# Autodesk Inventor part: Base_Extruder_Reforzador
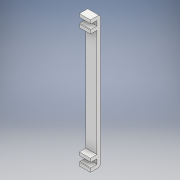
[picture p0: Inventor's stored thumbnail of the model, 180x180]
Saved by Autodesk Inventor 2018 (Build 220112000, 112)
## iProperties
Part Number: Base_Extruder_Reforzador
Material: Plástico ABS
Document SubType Name: Modeling
Designer: ULISES
Density: 1.06 g/cm^3
Appearance: Valor por defecto(1)
Mass: 170.779 g
Surface Area: 663.504 cm^2
Volume: 161.112 cm^3
Author: ULISES
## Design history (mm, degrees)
sketch "Boceto1"
  geometry: L1 (0, 0)-(60, 0); L2 (60, 0)-(60, 49); L3 (60, 49)-(0, 49); L4 (0, 49)-(0, 0); C1 r 1.6 at (50, 29); C2 r 1.6 at (10, 29); C3 r 12.5 at (30, 21); C4 r 13.5 at (30, -2); C5 r 1.6 at (45.5, 36.5); C6 r 1.6 at (14.5, 36.5); C7 r 1.6 at (45.5, 5.5); C8 r 1.6 at (14.5, 5.5)
  constraints: 8 centre point, 8 end point, 2 horizontal, 2 parallel, 1 horizontal alignment, 1 perpendicular, 1 vertical, 1 vertical alignment, 6 other
  dimensions: "d0" = 3.2 diameter of C1; "d1" = 3.2 diameter of C2 (= d0); "d2" = 25 diameter of C3; "d3" = 27 diameter of C4; "d10" = 20 horizontal distance of C3.centre C2.centre (= 0.5 x d15); "d14" = 60 distance of L2.end L3.end; "d15" = 40 distance of C2.centre C1.centre; "d16" = 10 distance from line of L4 C2.centre (= 0.5 x d14 - 0.5 x d15); "d17" = 3.2 diameter of C5; "d20" = 31 distance of C5.centre C6.centre; "d23" = 31 distance of C5.centre C7.centre; "d26" = 15.5 horizontal distance of C5.centre C3.centre (= 0.5 x d20); "d27" = 15.5 horizontal distance of C5.centre C3.centre (= 0.5 x d23); "d47" = 23 distance of C4.centre C3.centre; "d48" = 49 distance of L3.end L1.start; "d50" = 28 distance from line of L3 C3.centre; "d51" = 20 distance from line of L3 C1.centre; "d52" = 8 vertical distance of C3.centre C1.centre (derived)
extrude "Extrusión1" new body sketch "Boceto1" distance "d28" = 5; taper "d29" = 0 deg
sketch "Boceto2"
  geometry: C1 r 1.6 at (10, 29) reference; C2 r 1.6 at (50, 29) reference; C3 r 4.15 at (10, 29); C4 r 4.15 at (50, 29); 1 further point
  constraints: 2 centre point, 2 coincident
  dimensions: "d32" = 8.3 diameter of C3; "d33" = 8.3 diameter of C4
extrude "Extrusión2" cut sketch "Boceto2" distance "d30" = 6; taper "d31" = 0 deg
sketch "Boceto3"
  geometry: L1 (0, 0)-(-60, 0) reference; L2 (0, 49)-(0, 0) reference; L3 (-60, 49)-(0, 49) reference; L4 (-60, 0)-(-60, 49) reference; L5 (-60, 0)-(-60, 49) reference; L6 (-60, 49)-(0, 49); L7 (0, 49)-(0, 43); L8 (0, 43)-(-60, 43); L9 (-60, 43)-(-60, 49); C1 r 12.5 at (-30, 21) reference; C2 r 1.6 at (-14.5, 5.5) reference; C3 r 1.6 at (-45.5, 5.5) reference; C4 r 1.6 at (-14.5, 36.5) reference; C5 r 1.6 at (-45.5, 36.5) reference; 1 further point
  constraints: 8 end point, 2 parallel, 1 horizontal, 1 perpendicular, 1 point on line
  dimensions: "d34" = 6 distance between parallel lines of L3 L8
extrude "Extrusión3" join sketch "Boceto3" distance "d35" = 125; taper "d36" = 0 deg
sketch "Boceto4"
  geometry: L1 (0, 43)-(-60, 43) reference; L2 (-60, 0)-(-60, 43) reference; L3 (0, 0)-(-60, 0) reference; L4 (0, 43)-(0, 0) reference; L5 (0, 43)-(0, 49) reference; L6 (0, 49)-(-60, 49) reference; L7 (-60, 49)-(-60, 43) reference; L8 (-60, 43)-(0, 43) reference; L9 (-60, 0)-(-60, -13); L10 (-60, -13)-(0, -13); L11 (0, -13)-(0, 0); L12 (0, 0)-(-19.285, 0); L13 (-40.715, 0)-(-60, 0); L14 (0, 49)-(0, 0) reference; L15 (0, 0)-(0, 49); L16 (0, 49)-(-60, 49); L17 (-60, 49)-(-60, 0); L18 (-60, 0)-(-40.715, 0); L19 (-19.285, 0)-(0, 0); L20 (-30, -2)-(-40.9, -2); L21 (-40.9, -2)-(-40.9, -13); L22 (-40.9, -13)-(-30, -13); L23 (-30, -13)-(-30, -2); L24 (-30, -2)-(-19.1, -2); L25 (-19.1, -2)-(-19.1, -13); L26 (-19.1, -13)-(-30, -13); L27 (-30, -13)-(-30, -2); C1 r 12.5 at (-30, 21) reference; C2 r 1.6 at (-14.5, 5.5) reference; C3 r 1.6 at (-45.5, 5.5) reference; C4 r 1.6 at (-14.5, 36.5) reference; C5 r 1.6 at (-45.5, 36.5) reference; C6 r 4.5 at (-30, 21); A1 r 10.9 centre (-30, -2) between (-19.285, 0) and (-40.715, 0)
  constraints: 36 end point, 10 parallel, 6 horizontal, 6 perpendicular, 2 centre point, 2 collinear, 2 point on circle, 2 tangent, 1 coincident, 1 point on line, 1 vertical alignment
  dimensions: "d37" = 9 diameter of C6; "d54" = 13 distance of L9.start L9.end; "d55" = 60 distance of L9.end L10.end; "d62" = 23 distance of L20.start C1.centre; "d63" = 21.8 diameter of A1
extrude "Extrusión4" join sketch "Boceto4" distance "d39" = 5; taper "d40" = 0 deg
sketch "Boceto5"
  geometry: C1 r 4.15 at (-10, 29) reference; C2 r 4.15 at (-50, 29) reference; C3 r 6.15 at (-10, 29); C4 r 6.15 at (-50, 29); 1 further point
  constraints: 2 centre point
  dimensions: "d175" = 2 radial gap between concentric circles of C3 C1; "d176" = 2 radial gap between concentric circles of C2 C4
extrude "Extrusión5" join sketch "Boceto5" distance "d41" = 10; taper "d42" = 0 deg
sketch "Boceto6"
  geometry: L1 (-60, 43)-(0, 43) reference; L2 (-60, 43)-(0, 43); L3 (0, 43)-(0, 49); L4 (0, 49)-(-60, 49); L5 (-60, 49)-(-60, 43); L6 (-60, -13)-(-40.9, -13) reference; L7 (0, -13)-(0, 49) reference; L8 (0, 49)-(-60, 49) reference; L9 (-60, 49)-(-60, -13) reference; L10 (-40.9, -13)-(-40.9, -2) reference; L11 (-19.1, -2)-(-19.1, -13) reference; L12 (-19.1, -13)-(0, -13) reference; L13 (-40.9, -2)-(-19.1, -2) reference; C1 r 4.5 at (-30, 21) reference; 1 further point
  constraints: 8 end point, 2 parallel, 1 horizontal, 1 perpendicular
extrude "Extrusión6" join sketch "Boceto6" distance "d43" = 70; taper "d44" = 0 deg
sketch "Boceto7"
  geometry: L1 (0, 43)-(-60, 43) reference; L2 (-60, 43)-(0, 43) reference; L3 (0, 43)-(0, 49) reference; L4 (0, 49)-(-60, 49) reference; L5 (-60, 49)-(-60, 43) reference; L6 (-60, -13)-(-40.9, -13) reference; L7 (-60, 43)-(-60, -13) reference; L8 (0, -13)-(0, 43) reference; L9 (-40.9, -13)-(-40.9, -2) reference; L10 (-19.1, -2)-(-19.1, -13) reference; L11 (-60, -13)-(-40.9, -13) reference; L12 (-40.9, -2)-(-60, -2); L13 (-19.1, -2)-(0, -2); L14 (-60, 49)-(0, 49) reference; L15 (0, -2)-(0, 49); L16 (0, 49)-(-60, 49); L17 (-60, 49)-(-60, -2); L18 (-60, -2)-(-40.9, -2); L19 (-19.1, -2)-(0, -2); L20 (-19.1, -13)-(0, -13) reference; L21 (-40.9, -2)-(-19.1, -2) reference; C1 r 4.5 at (-30, 21) reference; A1 r 10.9 centre (-30, -2) between (-19.1, -2) and (-40.9, -2); 1 further point
  constraints: 14 end point, 3 horizontal, 3 parallel, 2 perpendicular, 2 point on circle, 1 centre point
  dimensions: "d177" = 10.9 radius of A1
extrude "Extrusión7" join sketch "Boceto7" distance "d45" = 5; taper "d46" = 0 deg
sketch "Boceto8"
  geometry: C1 r 1.6 at (-45.5, 5.5) reference; C2 r 1.6 at (-45.5, 36.5) reference; C3 r 1.6 at (-14.5, 36.5) reference; C4 r 1.6 at (-14.5, 5.5) reference; C5 r 3 at (-45.5, 5.5); C6 r 3 at (-45.5, 36.5); C7 r 3 at (-14.5, 36.5); C8 r 1.6 at (-14.5, 5.5) reference; C9 r 3 at (-14.5, 5.5); 1 further point
  constraints: 4 centre point, 4 coincident
  dimensions: "d56" = 6 diameter of C5; "d57" = 6 diameter of C6; "d58" = 6 diameter of C7; "d59" = 6 diameter of C9
extrude "Extrusión8" cut sketch "Boceto8" distance "d60" = 2.5; taper "d61" = 0 deg
sketch "Boceto9"
  geometry: L1 (18.5, 1)-(38.5, 1); L2 (38.5, 11)-(21.5, 11); L3 (48.5, 1)-(48.5, -13); L4 (11.5, -13)-(11.5, 1); L5 (9.5, -13)-(9.5, 1); L6 (21.5, 13)-(38.5, 13); L7 (50.5, 1)-(50.5, -13); L8 (48.5, -13)-(50.5, -13); L9 (9.5, -13)-(11.5, -13); L10 (19.1, -2)-(40.9, -2) reference; L11 (19.1, -13)-(19.1, -2) reference; L12 (19.1, -13)-(0, -13) reference; L13 (60, -13)-(40.9, -13) reference; L14 (40.9, -2)-(40.9, -13) reference; A1 r 10 centre (38.5, 1) between (48.5, 1) and (38.5, 11); A2 r 10 centre (21.5, 1) between (21.5, 11) and (11.5, 1); A3 r 12 centre (21.5, 1) between (21.5, 13) and (9.5, 1); A4 r 12 centre (38.5, 1) between (50.5, 1) and (38.5, 13); 1 further point
  constraints: 19 end point, 8 point on circle, 4 centre point, 4 tangent, 2 collinear, 2 parallel, 1 point on line, 4 other
  dimensions: "d64" = 20 distance of L1.start L1.end; "d66" = 2 radial gap between concentric circles of A1 A4; "d183" = 37 distance between parallel lines of L3 L4; "d184" = 21.8 distance between parallel lines of L14 L11 (derived); "d185" = 7.6 distance between parallel lines of L4 L11 (= 0.5 x d183 - 0.5 x d184); "d186" = 13 distance between parallel lines of L10 L2; "d187" = 10 radius of A2; "d188" = 10 radius of A1
extrude "Extrusión9" join sketch "Boceto9" distance "d67" = 2.2; taper "d68" = 0 deg
sketch "Boceto11" dims "d104" = 10.9 (derived)
  geometry: L1 (44, -2)-(54, -2); L2 (54, -2)-(54, 1); L3 (54, 1)-(43.572, 1); L4 (44, 1)-(44, -2); L5 (19.1, -2)-(9.1, -2); L6 (9.1, -2)-(9.1, 3); L7 (9.1, 3)-(17.03, 3); L8 (19.1, -2)-(0, -2) reference; L9 (19.1, -2)-(9.1, -2); L10 (9.1, -2)-(9.1, -7); L11 (9.1, -7)-(19.1, -7); L12 (19.1, -7)-(19.1, -2); L13 (60, -2)-(40.9, -2) reference; L14 (44, -2)-(40.9, -2); A1 r 13.9 centre (30, -2) between (43.572, 1) and (17.03, 3); 2 further points
  constraints: 24 end point, 4 horizontal, 4 parallel, 3 perpendicular, 2 point on circle, 1 centre point, 1 collinear, 1 vertical, 2 other
  dimensions: "d71" = 3 dimension on A1; "d72" = 3 distance of L1.end L2.end; "d73" = 10 distance of L2.end L4.start; "d75" = 5 distance of L5.end L6.end; "d84" = 10 distance from line of L6 L5.start; "d106" = 5 distance of L9.end L10.end; "d107" = 10 distance of L10.end L11.end
extrude "Extrusión11" join sketch "Boceto11" distance "d76" = 20; taper "d77" = 0 deg
node "Plano de trabajo1"
sketch "Boceto13"
  geometry: L1 (0, 49)-(-60, 49) reference; L2 (-60, 49)-(-60, -2) reference; L3 (-60, -2)-(-40.9, -2) reference; L4 (-19.1, -2)-(0, -2) reference; L5 (0, -2)-(0, 49) reference; L6 (-9.1, -2)-(-9.1, 3) reference; L7 (-19.1, -2)-(0, -2) reference; L8 (-17.03, 3)-(-9.1, 3) reference; L9 (-9.1, 3)-(-17.03, 3); L10 (-9.1, 3)-(-9.1, -7) reference; L11 (-9.1, 3)-(-9.1, -2); L12 (-9.1, -2)-(-21.1, -2); L13 (-21.1, -2)-(-21.1, -7); L14 (-21.1, -7)-(-9.1, -7); L15 (-9.1, -7)-(-9.1, -2); C1 r 4 at (-14.1, -2); C2 r 1.7 at (-14.1, -2); A1 r 10.9 centre (-30, -2) between (-19.1, -2) and (-40.9, -2) reference; A2 r 13.9 centre (-30, -2) between (-17.03, 3) and (-43.572, 1) reference; 1 further point
  constraints: 12 end point, 2 centre point, 2 horizontal, 2 parallel, 2 perpendicular, 1 coincident, 1 collinear
  dimensions: "d85" = 0 distance from line of L4 C1.centre; "d86" = 5 distance from line of L6 C1.centre; "d87" = 8 diameter of C1; "d88" = 3.4 diameter of C2; "d90" = 12 distance between parallel lines of L10 L13; "d108" = 5 distance of L12.end L13.end
extrude "Extrusión12" cut sketch "Boceto13" distance "d91" = 12; taper "d92" = 0 deg
sketch "Boceto14"
  geometry: L1 (40.9, -2)-(54, -2) reference; L2 (54, -2)-(54, 1) reference; L3 (54, 1)-(43.572, 1) reference; L4 (17.03, 3)-(9.1, 3) reference; L5 (9.1, 3)-(9.1, -7) reference; L6 (9.1, -7)-(19.1, -7) reference; L7 (19.1, -7)-(19.1, -2) reference; C1 r 1.75 at (14.1, -2); A1 r 13.9 centre (30, -2) between (43.572, 1) and (17.03, 3) reference; A2 r 10.9 centre (30, -2) between (40.9, -2) and (19.1, -2) reference; 1 further point
  constraints: 1 centre point
  dimensions: "d93" = 5 distance from line of L4 C1.centre; "d94" = 5 distance from line of L5 C1.centre; "d95" = 3.5 diameter of C1
extrude "Extrusión13" cut sketch "Boceto14" distance "d96" = 45.5; taper "d97" = 0 deg
sketch "Boceto15"
  geometry: L1 (16.886, -3.857)-(13.884, -5.342); L2 (13.884, -5.342)-(11.098, -3.484); L3 (11.098, -3.484)-(11.314, -0.143); L4 (11.314, -0.143)-(14.316, 1.342); L5 (14.316, 1.342)-(17.102, -0.516); L6 (17.102, -0.516)-(16.886, -3.857); C1 r 1.75 at (14.1, -2) reference; 2 further points
  constraints: 12 end point, 1 coincident, 13 other
  dimensions: "d98" = 5.8 distance between parallel lines of L3 L6
extrude "Extrusión14" cut sketch "Boceto15" distance "d99" = 4; taper "d100" = 0 deg
sketch "Boceto17"
  geometry: L1 (-19.1, -7)-(-19.1, -2) reference; L2 (-9.1, -7)-(-19.1, -7) reference; L3 (-9.1, -2)-(-9.1, -7) reference; L4 (-12.35, -2)-(-9.1, -2) reference; L5 (-19.1, -2)-(-15.85, -2) reference; A1 r 1.75 centre (-14.1, -2) between (-15.85, -2) and (-12.35, -2) reference; 1 further point
extrude "Extrusión16" join sketch "Boceto17" distance "d109" = 5; taper "d110" = 0 deg
sketch "Boceto16"
  geometry: C1 r 1.75 at (-14.1, -2) reference; C2 r 3 at (-14.1, -2); 1 further point
  constraints: 1 centre point, 1 coincident
  dimensions: "d101" = 6 diameter of C2
extrude "Extrusión15" cut sketch "Boceto16" distance "d102" = 4; taper "d103" = 0 deg
fillet "Empalme1" dims "d111" = 5
chamfer "Chaflán1" distance "d112" = 6; stored, may be unused: second distance "d113" = 2, angle "d114" = 45 deg
chamfer "Chaflán2" distance "d115" = 4; stored, may be unused: second distance "d116" = 2, angle "d117" = 45 deg
chamfer "Chaflán3" distance "d118" = 6; stored, may be unused: second distance "d119" = 2, angle "d120" = 45 deg
sketch "Boceto18"
  geometry: L1 (0, -52)-(0, 0) reference; L2 (-5, -52)-(-5, 0) reference; L3 (-80, 6)-(130, 6) reference; L4 (0, -19)-(-5, -19); L5 (-5, -19)-(-5, 6); L6 (-5, 6)-(0, 6); L7 (0, 6)-(0, -19); 2 further points
  constraints: 8 end point, 3 point on line, 2 parallel, 1 horizontal, 1 perpendicular
  dimensions: "d121" = 25 distance between parallel lines of L3 L4
extrude "Extrusión17" join sketch "Boceto18" distance "d122" = 14; taper "d123" = 0 deg
sketch "Boceto19"
  geometry: L1 (0, 49)-(-14, 49) reference; L2 (0, 49)-(0, 6) reference; C1 r 1.6 at (-1.6, 29); C2 r 1.6 at (-1.6, 39); 1 further point
  constraints: 2 centre point, 1 vertical alignment
  dimensions: "d124" = 3.2 diameter of C1; "d125" = 3.2 diameter of C2; "d126" = 10 distance from line of L1 C2.centre; "d127" = 10 distance of C2.centre C1.centre; "d128" = 1.6 distance from line of L2 C2.centre (= 0.5 x d125)
extrude "Extrusión18" cut sketch "Boceto19" distance "d129" = 15; taper "d130" = 0 deg
sketch "Boceto20"
  geometry: L1 (0, 5)-(-14, 5) reference; L2 (0, 5)-(-14, 5) reference; A1 r 25 centre (-7, 29) between (-14, 5) and (0, 5); 1 further point
  constraints: 2 point on circle, 1 centre point
extrude "Extrusión19" cut sketch "Boceto20" distance "d131" = 25; taper "d132" = 0 deg
sketch "Boceto21"
  geometry: L1 (3.75, -125)-(16.25, -125); L2 (16.25, -125)-(16.25, -117); L3 (16.25, -117)-(3.75, -117); L4 (3.75, -117)-(3.75, -125); L5 (19.1, -125)-(11.5, -125) reference; L6 (60, -125)-(0, -125) reference; L7 (0, 0)-(0, -125) reference
  constraints: 8 end point, 2 collinear, 2 parallel, 1 horizontal, 1 perpendicular
  dimensions: "d133" = 8 distance of L1.end L2.end; "d134" = 12.5 distance of L2.end L3.end; "d189" = 3.75 distance between parallel lines of L7 L4
extrude "Extrusión20" join sketch "Boceto21" distance "d137" = 1.5; taper "d138" = 0 deg
sketch "Boceto22"
  geometry: L1 (16.25, -125)-(16.25, -117) reference; L2 (16.25, -117)-(3.75, -117) reference; L3 (3.75, -117)-(3.75, -125) reference; L4 (16.25, -125)-(3.75, -125) reference; C1 r 1 at (6.75, -122); C2 r 1 at (13.25, -122); 1 further point
  constraints: 2 centre point, 1 horizontal alignment
  dimensions: "d139" = 6.5 distance of C1.centre C2.centre; "d140" = 3 distance from line of L3 C1.centre (= 0.5 x d144 - 0.5 x d139); "d142" = 2 diameter of C2; "d143" = 2 diameter of C1; "d144" = 12.5 distance of L1.end L2.end (derived); "d205" = 3 distance from line of L4 C1.centre
extrude "Extrusión21" cut sketch "Boceto22" distance "d145" = 5; taper "d146" = 0 deg
sketch "Boceto26"
  geometry: L1 (60, -75)-(60, 135) reference; L2 (60, -75)-(72.25, -75); L3 (72.25, -75)-(72.25, -55); L4 (72.25, -55)-(60, -55); L5 (60, -55)-(60, -75); L6 (0, -75)-(-12.25, -75); L7 (-12.25, -75)-(-12.25, -55); L8 (-12.25, -55)-(0, -55); L9 (0, -55)-(0, -75); L10 (0, 0)-(0, -70) reference; 2 further points
  constraints: 16 end point, 4 parallel, 2 horizontal, 2 perpendicular, 2 point on line, 1 collinear
  dimensions: "d166" = 12.25 distance of L3.end L4.end; "d167" = 20 distance of L2.end L3.end; "d168" = 12.25 distance of L7.end L8.end; "d169" = 20 distance of L6.end L7.end (derived)
extrude "Extrusión24" join sketch "Boceto26" distance "d170" = 6; taper "d171" = 0 deg
sketch "Boceto23"
  geometry: L1 (60, 205)-(0, 205) reference; L2 (0, 135)-(60, 135) reference; L3 (60, 205)-(60, 0) reference; C1 r 1.7 at (-8, 200); C2 r 1.7 at (68, 200); C3 r 1.7 at (30, 140.75); 3 further points
  constraints: 3 centre point, 1 horizontal alignment
  dimensions: "d147" = 76 distance of C2.centre C1.centre; "d148" = 38 horizontal distance of C1.centre C3.centre (= 0.5 x d147); "d149" = 59.25 vertical distance of C1.centre C3.centre; "d150" = 60 distance of L1.start L1.end (derived); "d151" = 70 distance between parallel lines of L1 L2 (derived); "d152" = 5 distance from line of L1 C1.centre; "d154" = 3.4 diameter of C1; "d155" = 3.4 diameter of C2; "d156" = 3.4 diameter of C3; "d164" = 60 distance of L2.start L2.end (derived); "d165" = 30 distance from line of L3 C3.centre (= 0.5 x d164)
extrude "Extrusión22" cut sketch "Boceto23" distance "d157" = 10; taper "d158" = 0 deg
sketch "Boceto25"
  geometry: L1 (31.703, -8.7)-(28.297, -8.7); L2 (28.297, -8.7)-(26.594, -5.75); L3 (26.594, -5.75)-(28.297, -2.8); L4 (28.297, -2.8)-(31.703, -2.8); L5 (31.703, -2.8)-(33.406, -5.75); L6 (33.406, -5.75)-(31.703, -8.7); L7 (69.703, -67.95)-(66.297, -67.95); L8 (66.297, -67.95)-(64.594, -65); L9 (64.594, -65)-(66.297, -62.05); L10 (66.297, -62.05)-(69.703, -62.05); L11 (69.703, -62.05)-(71.406, -65); L12 (71.406, -65)-(69.703, -67.95); L13 (-9.703, -67.95)-(-11.406, -65); L14 (-11.406, -65)-(-9.703, -62.05); L15 (-9.703, -62.05)-(-6.297, -62.05); L16 (-6.297, -62.05)-(-4.594, -65); L17 (-4.594, -65)-(-6.297, -67.95); L18 (-6.297, -67.95)-(-9.703, -67.95); C1 r 1.7 at (30, -5.75) reference; C2 r 1.7 at (68, -65) reference; C3 r 1.7 at (-8, -65) reference; C4 r 1.7 at (-8, -65) reference; 4 further points
  constraints: 36 end point, 3 coincident, 3 horizontal, 39 other
  dimensions: "d159" = 5.9 distance between parallel lines of L18 L15; "d160" = 5.9 distance between parallel lines of L7 L10; "d161" = 5.9 distance between parallel lines of L1 L4
extrude "Extrusión23" cut sketch "Boceto25" distance "d162" = 2.5; taper "d163" = 0 deg
sketch "Boceto27"
  geometry: L1 (48.5, -13)-(48.5, 1) reference; L2 (38.5, 11)-(21.5, 11) reference; L3 (11.5, 1)-(11.5, -13) reference; L4 (19.1, -13)-(11.5, -13) reference; L5 (19.1, -13)-(19.1, -2) reference; L6 (19.1, -2)-(40.9, -2) reference; L7 (40.9, -2)-(40.9, -13) reference; L8 (48.5, -13)-(40.9, -13) reference; L9 (21.5, 11)-(38.5, 11) reference; L10 (48.5, 1)-(48.5, -13) reference; L11 (48.5, -13)-(50.5, -13) reference; L12 (50.5, -13)-(50.5, 1) reference; L13 (38.5, 13)-(21.5, 13) reference; L14 (9.5, 1)-(9.5, -13) reference; L15 (9.5, -13)-(11.5, -13) reference; L16 (11.5, -13)-(11.5, 1) reference; A1 r 10 centre (38.5, 1) between (48.5, 1) and (38.5, 11) reference; A2 r 10 centre (21.5, 1) between (21.5, 11) and (11.5, 1) reference; A3 r 10 centre (38.5, 1) between (48.5, 1) and (38.5, 11) reference; A4 r 12 centre (38.5, 1) between (50.5, 1) and (38.5, 13) reference; A5 r 12 centre (21.5, 1) between (21.5, 13) and (9.5, 1) reference; A6 r 10 centre (21.5, 1) between (21.5, 11) and (11.5, 1) reference; 1 further point
extrude "Extrusión25" join sketch "Boceto27" distance "d173" = 1.5; taper "d174" = 0 deg
sketch "Boceto28"
  geometry: L1 (-19.1, -2)-(-40.9, -2) reference; L2 (-19.4, -2)-(-19.1, -2); L3 (-40.6, -2)-(-40.9, -2); A1 r 10.9 centre (-30, -2) between (-19.1, -2) and (-40.9, -2) reference; A2 r 10.6 centre (-30, -2) between (-19.4, -2) and (-40.6, -2); 1 further point
  constraints: 4 end point, 2 collinear, 2 point on circle, 1 centre point
  dimensions: "d190" = 0.3 radial gap between concentric circles of A1 A2
extrude "Extrusión26" join sketch "Boceto28" distance "d191" = 25; taper "d192" = 0 deg
chamfer "Chaflán4" distance "d193" = 0.3; stored, may be unused: second distance "d194" = 2, angle "d195" = 45 deg
sketch "Boceto29"
  geometry: L1 (-40.9, -2)-(-19.1, -2) reference; C1 r 10.9 at (-30, -2); 1 further point
  constraints: 1 centre point, 1 midpoint
  dimensions: "d196" = 21.8 diameter of C1
extrude "Extrusión27" cut sketch "Boceto29" distance "d197" = 25; taper "d198" = 0 deg
chamfer "Chaflán5" distance "d199" = 5; stored, may be unused: second distance "d200" = 2, angle "d201" = 45 deg
chamfer "Chaflán6" distance "d202" = 5; stored, may be unused: second distance "d203" = 2, angle "d204" = 45 deg
sketch "Boceto30"
  geometry: L1 (0, 43)-(60, 43) reference; L2 (16.25, 41.5)-(3.75, 41.5) reference; L3 (16.25, 40.5)-(0.75, 40.5); L4 (0.75, 40.5)-(0.75, 36.5); L5 (0.75, 36.5)-(16.25, 36.5); L6 (16.25, 36.5)-(16.25, 40.5); 1 further point
  constraints: 8 end point, 2 parallel, 1 horizontal, 1 perpendicular, 1 vertical alignment
  dimensions: "d206" = 15.5 distance of L4.end L5.end; "d207" = 1 distance between parallel lines of L2 L3; "d208" = 4 distance of L5.end L3.start
extrude "Extrusión28" cut sketch "Boceto30" distance "d209" = 25; taper "d210" = 0 deg
sketch "Boceto31"
  geometry: L1 (180, 6)-(180, 0) reference; L2 (180, 6)-(-5, 6) reference; L3 (-5, -37)-(-5, 6) reference; L4 (0, -37)-(-5, -37) reference; L5 (0, -37)-(0, 0) reference; L6 (0, 0)-(125, 0) reference; L7 (125, 0)-(125, -52) reference; L8 (130, -52)-(125, -52) reference; L9 (130, 0)-(130, -52) reference; L10 (130, 0)-(180, 0) reference; L11 (0, 0)-(0, -37) reference; L12 (0, 0)-(-11.308, 0); L13 (-11.308, 0)-(-11.308, -48.971); L14 (-11.308, -48.971)-(0, -48.971); L15 (0, -48.971)-(0, 0); L16 (130, 0)-(108.123, 0); L17 (108.123, 0)-(108.123, -59.324); L18 (108.123, -59.324)-(130, -59.324); L19 (130, -59.324)-(130, 0); L20 (130, 0)-(130, -52) reference; L21 (130, 0)-(210.979, 0); L22 (210.979, 0)-(210.979, 30.736); L23 (210.979, 30.736)-(130, 30.736); L24 (130, 30.736)-(130, 0); L25 (130, 0)-(213.845, 0); L26 (213.845, 0)-(213.845, -59.324); L27 (213.845, -59.324)-(130, -59.324); L28 (130, -59.324)-(130, 0); 1 further point
  constraints: 32 end point, 8 parallel, 4 horizontal, 4 perpendicular, 1 point on line
extrude "Extrusión29" cut sketch "Boceto31" stored distance "d211" = 500; taper "d212" = 0 deg
sketch "Boceto32"
  geometry: L1 (60, 0)-(60, -135) reference; L2 (0, 0)-(60, 0) reference; L3 (0, -130)-(0, 0) reference; L4 (-14, -135)-(-14, -130) reference; L5 (-14, -135)-(60, -135) reference; L6 (0, 0)-(60, 0) reference; L7 (48, 0)-(-14, 0); L8 (-14, 0)-(-14, -135); L9 (-14, -135)-(48, -135); L10 (48, -135)-(48, 0); C1 r 1 at (13.25, -127) reference; C2 r 1 at (6.75, -127) reference; A1 r 25 centre (-7, -106) between (-14, -130) and (0, -130) reference; 1 further point
  constraints: 8 end point, 2 collinear, 2 parallel, 1 horizontal, 1 perpendicular, 1 point on line
  dimensions: "d213" = 12 distance between parallel lines of L1 L10
extrude "Extrusión30" cut sketch "Boceto32" distance "d214" = 20; taper "d215" = 0 deg
sketch "Boceto34"
  geometry: L1 (0, 0)-(0, 6) reference; L2 (0, 6)-(-4, 6); L3 (-4, 6)-(-4, -5); L4 (-4, -5)-(0, -5); L5 (0, -5)-(0, 6); L6 (135, 6)-(0, 6) reference; L7 (5.2, 6)-(9.2, 6); L8 (9.2, 6)-(9.2, -5); L9 (9.2, -5)-(5.2, -5); L10 (5.2, -5)-(5.2, 6); L11 (129.8, 6)-(125.8, 6); L12 (125.8, 6)-(125.8, -5); L13 (125.8, -5)-(129.8, -5); L14 (129.8, -5)-(129.8, 6); L15 (135, 6)-(139, 6); L16 (139, 6)-(139, -5); L17 (139, -5)-(135, -5); L18 (135, -5)-(135, 6); 1 further point
  constraints: 32 end point, 8 parallel, 4 horizontal, 4 perpendicular, 2 point on line, 1 collinear
  dimensions: "d218" = 4 distance of L1.end L2.end; "d219" = 11 distance of L2.end L3.end; "d220" = 5.2 distance between parallel lines of L1 L10; "d221" = 4 distance of L8.end L9.end; "d224" = 4 distance between parallel lines of L14 L12; "d225" = 11 distance of L11.end L12.end; "d227" = 5.2 distance between parallel lines of L18 L14; "d228" = 11 distance of L15.end L16.end; "d229" = 4 distance of L6.start L15.end
extrude "Extrusión31" join sketch "Boceto34" distance "d230" = 12; taper "d231" = 0 deg
chamfer "Chaflán7" distance "d232" = 2; stored, may be unused: second distance "d233" = 2, angle "d234" = 45 deg
chamfer "Chaflán8" distance "d235" = 0.5; stored, may be unused: second distance "d236" = 2, angle "d237" = 45 deg
sketch "Boceto35"
  geometry: L1 (0, 4)-(12, 4) reference; L2 (12, 9.2)-(12, 4) reference; L3 (0, 9.2)-(12, 9.2) reference; L4 (0, 9.2)-(0, 4) reference; L5 (12, 0)-(0, 0) reference; L6 (0, 0)-(0, -116.6) reference; L7 (0, -116.6)-(12, -116.6) reference; L8 (12, 0)-(12, -116.6) reference; L9 (12, -120.6)-(0, -120.6) reference; L10 (0, -120.6)-(0, -125.8) reference; L11 (0, -125.8)-(12, -125.8) reference; L12 (12, -120.6)-(12, -125.8) reference; 1 further point
extrude "Extrusión32" cut sketch "Boceto35" distance "d238" = 2; taper "d239" = 0 deg
node "Sólido1"
node "Contorno proyectado1"
node "Contorno proyectado2"
node "Contorno proyectado3"
node "Contorno proyectado4"
node "Contorno proyectado5"
node "Contorno proyectado6"
node "Contorno proyectado11"
node "Contorno proyectado12"
node "Contorno proyectado13"
node "Contorno proyectado14"
node "Contorno proyectado15"
node "Contorno proyectado16"
node "Contorno proyectado17"
node "Contorno proyectado18"
node "Contorno proyectado19"
node "Contorno proyectado20"
node "Contorno proyectado21"
other parameters: "d81" = -6
